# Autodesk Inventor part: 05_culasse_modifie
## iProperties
Created: 2002-11
Part Number: 05_culasse_modifie
Material: Z-A 4G
Document SubType Name: Modélisation
Designer: poste-2
Control State: 0
Master: False
Checked Out: False
Shininess: 20.0
Length Units: 11269
Angle Units: 11279
Time Units: 11290
Mass Units: 11283
Length Display Precision: 3
Angle Display Precision: 2
Compacted: True
Density: 7.8500000000000005
Volumn: 3.2257814935651448
Area: 30.84428910282234
PropertySet Name: Model Information
Author: poste-2
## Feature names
1. Révolution1 [Revolution]
2. Extrusion1
3. Extrusion2
4. Réseau circulaire1 [Circular Pattern]
5. Extrusion5
6. Perçage2 [Hole]
7. Révolution2 [Revolution]
8. Révolution3 [Revolution]
9. Extrusion6
10. Extrusion8
